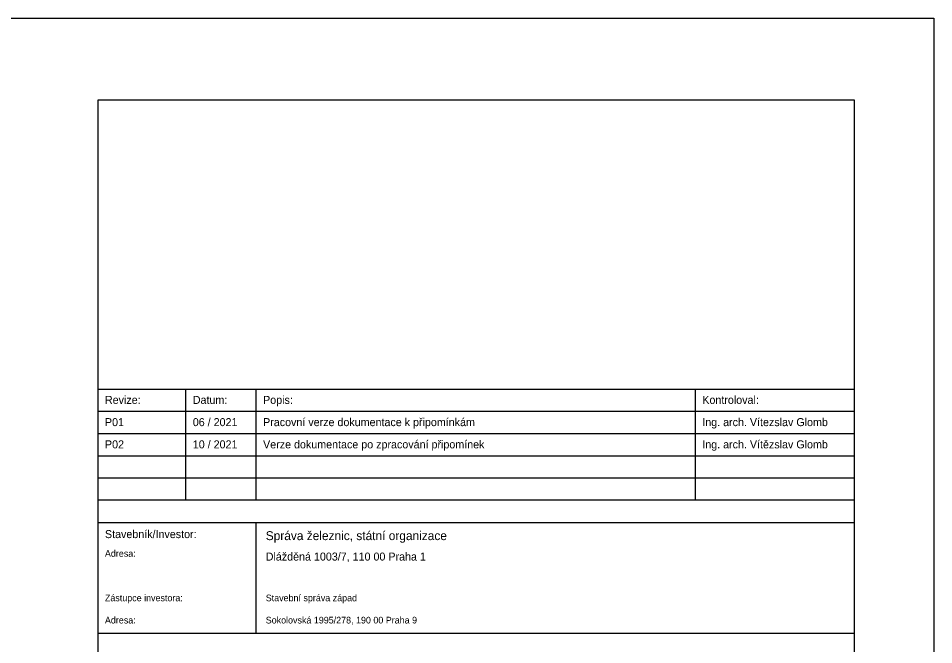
# Model space of a CAD drawing. Extents: x -823399 to -812899, y -1074543 to -1067118.
# Drawn here: x -818044 to -812899, y -1070640 to -1067118 of the extents above; entities that cross this region are included whole.
import ezdxf

# ---------------------------------------------------------------- set-up
doc = ezdxf.new("R2010")
doc.units = 0
doc.layers.add('formát', color=7, linetype='Continuous')
doc.layers.add('Popisove_pole', color=7, linetype='Continuous')

msp = doc.modelspace()

# ---------------------------------------------------------------- linework, layer by layer
at = {"layer": 'formát'}
msp.add_lwpolyline([(-818148.7, -1067117.7), (-812898.7, -1067117.7), (-812898.7, -1074542.7), (-818148.7, -1074542.7)], close=True, dxfattribs=at)
at = {"layer": 'Popisove_pole'}
for p, q in [((-817101.6, -1069827), (-817101.6, -1069202)), ((-816706.6, -1069827), (-816706.6, -1069202)), ((-814237.8, -1069827), (-814237.8, -1069202)), ((-817595.3, -1069327), (-813345.3, -1069327)), ((-817595.3, -1069452), (-813345.3, -1069452)), ((-817595.3, -1069577), (-813345.3, -1069577)), ((-817595.3, -1069702), (-813345.3, -1069702)), ((-816706.6, -1070577), (-816706.6, -1069952))]:
    msp.add_line(p, q, dxfattribs=at)
for points in [[(-817595.3, -1067577), (-813345.3, -1067577), (-813345.3, -1074077), (-817595.3, -1074077)], [(-817595.3, -1069202), (-813345.3, -1069202), (-813345.3, -1069827), (-817595.3, -1069827)], [(-817595.3, -1069952), (-813345.3, -1069952), (-813345.3, -1070577), (-817595.3, -1070577)]]:
    msp.add_lwpolyline(points, close=True, dxfattribs=at)

# ---------------------------------------------------------------- texts
for s, height, p in [('Revize:', 45, (-817556.7, -1069285.7)), ('Datum:', 45, (-817062.9, -1069285.7)), ('Popis:', 45, (-816667.9, -1069285.7)), ('Kontroloval:', 45, (-814199.2, -1069285.7)), ('P01', 45, (-817556.7, -1069410.7)), ('06 / 2021', 45, (-817062.9, -1069410.7)), ('Pracovní verze dokumentace k připomínkám', 45, (-816667.9, -1069410.7)), ('Ing. arch. Vítezslav Glomb', 45, (-814199.2, -1069410.7)), ('P02', 45, (-817556.7, -1069535.7)), ('10 / 2021', 45, (-817062.9, -1069535.7)), ('Verze dokumentace po zpracování připomínek', 45, (-816667.9, -1069535.7)), ('Ing. arch. Vítězslav Glomb', 45, (-814199.2, -1069535.7)), ('Stavebník/Investor:', 45, (-817556.7, -1070040.2)), ('Správa železnic, státní organizace', 50, (-816652.9, -1070051.5)), ('Adresa:', 37.5, (-817556.7, -1070145.2)), ('Dlážděná 1003/7, 110 00 Praha 1', 45, (-816652.9, -1070166.5)), ('Zástupce investora:', 37.5, (-817556.7, -1070395.2)), ('Stavební správa západ', 37.5, (-816652.9, -1070395.2)), ('Adresa:', 37.5, (-817556.7, -1070520.2)), ('Sokolovská 1995/278, 190 00 Praha 9', 37.5, (-816652.9, -1070520.2))]:
    msp.add_text(s, height=height, rotation=360, dxfattribs=at).set_placement(p)

doc.saveas('drawing.dxf')
